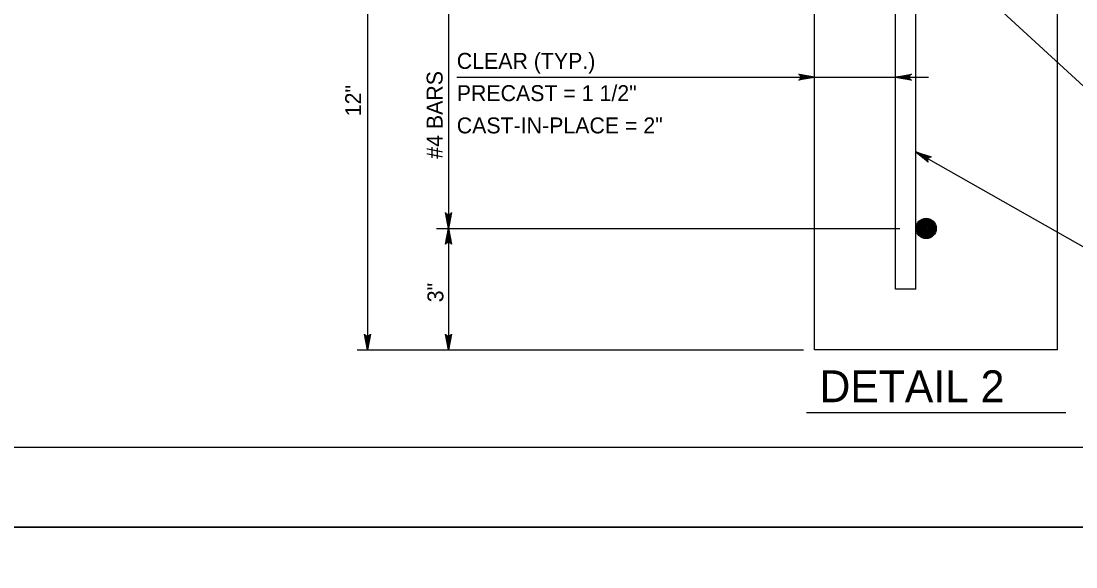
# Model space of a CAD drawing. Extents: x 2087776 to 2104538, y 970919 to 982612.
# Drawn here: x 2094243 to 2094894, y 980639 to 980976 of the extents above; entities that cross this region are included whole.
import ezdxf

# ---------------------------------------------------------------- set-up
doc = ezdxf.new("R2010")
doc.units = 0
doc.layers.add('1', color=7, linetype='Continuous')
doc.layers.add('PLT-BNDY', color=7, linetype='Continuous')

msp = doc.modelspace()

# ---------------------------------------------------------------- linework, layer by layer
at = {"layer": '1'}
for p, q in [((2094456.54, 981128.97), (2094456.54, 980772.74)), ((2094732.55, 980772.74), (2094732.55, 981128.97)), ((2094782.55, 980810.24), (2094782.55, 981082.51)), ((2094795.05, 980810.24), (2094795.05, 981082.51)), ((2094506.54, 981072.74), (2094506.54, 980772.74)), ((2094926.76, 980909.64), (2094805.26, 981021.18)), ((2094882.55, 980772.74), (2094882.55, 981003.97)), ((2094511.75, 980941.09), (2094802.88, 980941.09)), ((2094795.05, 980895.07), (2094945.36, 980809.77)), ((2094499.17, 980847.74), (2094785.13, 980847.74)), ((2094795.05, 980810.24), (2094782.55, 980810.24)), ((2094450.17, 980772.74), (2094725.66, 980772.74)), ((2094882.55, 980772.74), (2094732.55, 980772.74)), ((2094727.51, 980734.08), (2094887.75, 980734.08))]:
    msp.add_line(p, q, dxfattribs=at)
for points in [[(2096000.74, 980712.64), (2096000.74, 982563.04), (2093422, 982563.04), (2093422, 980712.64), (2096000.74, 980712.64), (2096000.74, 980799.12), (2095344.57, 980799.12), (2095344.57, 981011.32), (2096000.74, 981011.32), (2096000.74, 981106.34), (2095344.57, 981106.34), (2095344.57, 980712.64), (2095603.11, 980712.64), (2095603.11, 980799.12), (2095603.11, 980712.64), (2095855.73, 980712.64), (2095855.73, 980799.12), (2095855.73, 980758.72), (2096000.74, 980758.72)], [(2094732.55, 980941.09), (2094722.76, 980939.25), (2094723.14, 980939.51), (2094723.52, 980939.77), (2094723.71, 980940.1), (2094723.91, 980940.43), (2094723.96, 980940.76), (2094724.02, 980941.09), (2094723.96, 980941.41), (2094723.91, 980941.74), (2094723.71, 980942.07), (2094723.52, 980942.4), (2094723.14, 980942.66), (2094722.76, 980942.92), (2094732.55, 980941.09), (2094723.14, 980942.66), (2094723.52, 980942.4), (2094732.55, 980941.09), (2094723.71, 980942.07), (2094723.91, 980941.74), (2094732.55, 980941.09), (2094723.96, 980941.41), (2094724.02, 980941.09), (2094732.55, 980941.09), (2094723.96, 980940.76), (2094723.91, 980940.43), (2094732.55, 980941.09), (2094723.71, 980940.1), (2094723.52, 980939.77), (2094732.55, 980941.09), (2094723.14, 980939.51)], [(2094782.55, 980941.09), (2094792.34, 980942.92), (2094791.96, 980942.66), (2094791.58, 980942.4), (2094791.39, 980942.07), (2094791.19, 980941.74), (2094791.14, 980941.41), (2094791.08, 980941.09), (2094791.14, 980940.76), (2094791.19, 980940.43), (2094791.39, 980940.1), (2094791.58, 980939.77), (2094791.96, 980939.51), (2094792.34, 980939.25), (2094782.55, 980941.09), (2094791.96, 980939.51), (2094791.58, 980939.77), (2094782.55, 980941.09), (2094791.39, 980940.1), (2094791.19, 980940.43), (2094782.55, 980941.09), (2094791.14, 980940.76), (2094791.08, 980941.09), (2094782.55, 980941.09), (2094791.14, 980941.41), (2094791.19, 980941.74), (2094782.55, 980941.09), (2094791.39, 980942.07), (2094791.58, 980942.4), (2094782.55, 980941.09), (2094791.96, 980942.66)], [(2094795.05, 980895.07), (2094804.47, 980891.84), (2094804.01, 980891.8), (2094803.55, 980891.76), (2094803.22, 980891.57), (2094802.89, 980891.38), (2094802.68, 980891.12), (2094802.47, 980890.86), (2094802.36, 980890.55), (2094802.24, 980890.23), (2094802.25, 980889.85), (2094802.26, 980889.47), (2094802.46, 980889.06), (2094802.65, 980888.65), (2094795.05, 980895.07), (2094802.46, 980889.06), (2094802.26, 980889.47), (2094795.05, 980895.07), (2094802.25, 980889.85), (2094802.24, 980890.23), (2094795.05, 980895.07), (2094802.36, 980890.55), (2094802.47, 980890.86), (2094795.05, 980895.07), (2094802.68, 980891.12), (2094802.89, 980891.38), (2094795.05, 980895.07), (2094803.22, 980891.57), (2094803.55, 980891.76), (2094795.05, 980895.07), (2094804.01, 980891.8)], [(2094506.54, 980847.74), (2094504.71, 980857.52), (2094504.97, 980857.15), (2094505.23, 980856.77), (2094505.56, 980856.58), (2094505.88, 980856.38), (2094506.21, 980856.32), (2094506.54, 980856.27), (2094506.87, 980856.32), (2094507.2, 980856.38), (2094507.53, 980856.58), (2094507.85, 980856.77), (2094508.11, 980857.15), (2094508.38, 980857.52), (2094506.54, 980847.74), (2094508.11, 980857.15), (2094507.85, 980856.77), (2094506.54, 980847.74), (2094507.53, 980856.58), (2094507.2, 980856.38), (2094506.54, 980847.74), (2094506.87, 980856.32), (2094506.54, 980856.27), (2094506.54, 980847.74), (2094506.21, 980856.32), (2094505.88, 980856.38), (2094506.54, 980847.74), (2094505.56, 980856.58), (2094505.23, 980856.77), (2094506.54, 980847.74), (2094504.97, 980857.15)], [(2094506.54, 980847.74), (2094508.38, 980837.95), (2094508.11, 980838.33), (2094507.85, 980838.71), (2094507.53, 980838.9), (2094507.2, 980839.1), (2094506.87, 980839.15), (2094506.54, 980839.21), (2094506.21, 980839.15), (2094505.88, 980839.1), (2094505.56, 980838.9), (2094505.23, 980838.71), (2094504.97, 980838.33), (2094504.71, 980837.95), (2094506.54, 980847.74), (2094504.97, 980838.33), (2094505.23, 980838.71), (2094506.54, 980847.74), (2094505.56, 980838.9), (2094505.88, 980839.1), (2094506.54, 980847.74), (2094506.21, 980839.15), (2094506.54, 980839.21), (2094506.54, 980847.74), (2094506.87, 980839.15), (2094507.2, 980839.1), (2094506.54, 980847.74), (2094507.53, 980838.9), (2094507.85, 980838.71), (2094506.54, 980847.74), (2094508.11, 980838.33)], [(2094456.54, 980772.74), (2094454.71, 980782.52), (2094454.97, 980782.15), (2094455.23, 980781.77), (2094455.56, 980781.58), (2094455.88, 980781.38), (2094456.21, 980781.32), (2094456.54, 980781.27), (2094456.87, 980781.32), (2094457.2, 980781.38), (2094457.53, 980781.58), (2094457.85, 980781.77), (2094458.11, 980782.15), (2094458.38, 980782.52), (2094456.54, 980772.74), (2094458.11, 980782.15), (2094457.85, 980781.77), (2094456.54, 980772.74), (2094457.53, 980781.58), (2094457.2, 980781.38), (2094456.54, 980772.74), (2094456.87, 980781.32), (2094456.54, 980781.27), (2094456.54, 980772.74), (2094456.21, 980781.32), (2094455.88, 980781.38), (2094456.54, 980772.74), (2094455.56, 980781.58), (2094455.23, 980781.77), (2094456.54, 980772.74), (2094454.97, 980782.15)], [(2094506.54, 980772.74), (2094504.71, 980782.52), (2094504.97, 980782.15), (2094505.23, 980781.77), (2094505.56, 980781.58), (2094505.88, 980781.38), (2094506.21, 980781.32), (2094506.54, 980781.27), (2094506.87, 980781.32), (2094507.2, 980781.38), (2094507.53, 980781.58), (2094507.85, 980781.77), (2094508.11, 980782.15), (2094508.38, 980782.52), (2094506.54, 980772.74), (2094508.11, 980782.15), (2094507.85, 980781.77), (2094506.54, 980772.74), (2094507.53, 980781.58), (2094507.2, 980781.38), (2094506.54, 980772.74), (2094506.87, 980781.32), (2094506.54, 980781.27), (2094506.54, 980772.74), (2094506.21, 980781.32), (2094505.88, 980781.38), (2094506.54, 980772.74), (2094505.56, 980781.58), (2094505.23, 980781.77), (2094506.54, 980772.74), (2094504.97, 980782.15)]]:
    msp.add_lwpolyline(points, dxfattribs=at)
for radius in [6.25, 5.81, 5.36, 4.92, 4.48, 4.03, 3.59, 3.14, 2.7, 2.26, 1.81, 1.37, 0.924, 0.48]:
    msp.add_circle((2094801.39, 980847.74), radius, dxfattribs=at)
at = {"layer": 'PLT-BNDY'}
for points in [[(2093294.05, 982612.25), (2096053.23, 982612.25), (2096053.23, 980663.43), (2093294.05, 980663.43)], [(2093294.05, 980663.43), (2096053.23, 980663.43), (2096053.23, 978714.61), (2093294.05, 978714.61)]]:
    msp.add_lwpolyline(points, close=True, dxfattribs=at)

# ---------------------------------------------------------------- texts
at = {"layer": '1'}
for s, height, p in [('CLEAR (TYP.)', 9.8425, (2094511.64, 980946.24)), ('PRECAST = 1 1/2"', 9.8425, (2094511.64, 980926.32)), ('CAST-IN-PLACE = 2" ', 9.8425, (2094511.64, 980906.4)), ('DETAIL 2', 19.685, (2094735.62, 980740.48))]:
    msp.add_text(s, height=height, dxfattribs=at).set_placement(p)
for s, p in [('#4 BARS', (2094502.91, 980890.77)), ('12"', (2094452.61, 980916.98)), ('3"', (2094503.37, 980802.16))]:
    msp.add_text(s, height=9.843, rotation=90, dxfattribs=at).set_placement(p)

doc.saveas('drawing.dxf')
